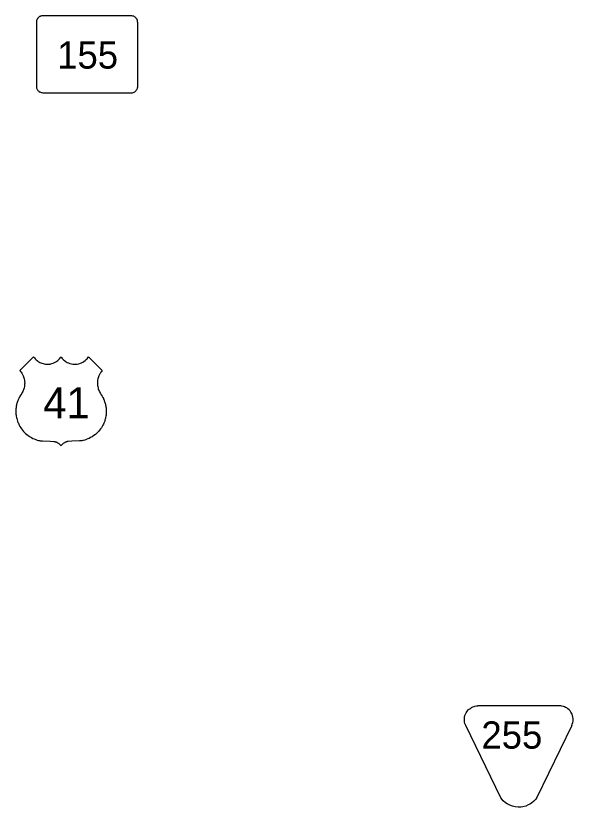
# Model space of a CAD drawing. Extents: x 1612280 to 1883141, y 560852 to 780851.
# Drawn here: x 1762915 to 1770463, y 642827 to 653552 of the extents above; entities that cross this region are included whole.
import ezdxf

# ---------------------------------------------------------------- set-up
doc = ezdxf.new("R2010")
doc.units = 0
for name, color, linetype in [('DESIGN - ROW - Easement Linework and Patterning', 7, 'Continuous'), ('DESIGN - ROW - Slope Lines', 7, 'Continuous'), ('SURVEY - DRAINAGE - Bridge Deck with Text', 7, 'Continuous')]:
    doc.layers.add(name, color=color, linetype=linetype)

msp = doc.modelspace()

# ---------------------------------------------------------------- linework, layer by layer
at = {"layer": 'DESIGN - ROW - Easement Linework and Patterning'}
for points in [[(1769482, 642953), (1769007, 643933), (1768997, 643960), (1768992, 643978), (1768989, 643996), (1768989, 644012), (1768989, 644030), (1768991, 644046), (1768997, 644069), (1769004, 644087), (1769012, 644103), (1769022, 644119), (1769032, 644133), (1769047, 644149), (1769062, 644161), (1769075, 644170), (1769088, 644178), (1769104, 644185), (1769120, 644191), (1769132, 644194), (1769154, 644198), (1769173, 644199)], [(1769482, 642953), (1769007, 643933), (1768997, 643960), (1768992, 643978), (1768989, 643996), (1768989, 644012), (1768989, 644030), (1768991, 644046), (1768997, 644069), (1769004, 644087), (1769012, 644103), (1769022, 644119), (1769032, 644133), (1769047, 644149), (1769062, 644161), (1769075, 644170), (1769088, 644178), (1769104, 644185), (1769120, 644191), (1769132, 644194), (1769154, 644198), (1769173, 644199)], [(1770444, 643933), (1770450, 643951), (1770458, 643974), (1770461, 643991), (1770463, 644011), (1770462, 644027), (1770460, 644045), (1770455, 644067), (1770448, 644085), (1770441, 644100), (1770433, 644115), (1770421, 644131), (1770409, 644144), (1770390, 644161), (1770375, 644171), (1770361, 644179), (1770347, 644185), (1770330, 644191), (1770311, 644196), (1770297, 644198), (1770278, 644199), (1769173, 644199)], [(1770444, 643933), (1770450, 643951), (1770458, 643974), (1770461, 643991), (1770463, 644011), (1770462, 644027), (1770460, 644045), (1770455, 644067), (1770448, 644085), (1770441, 644100), (1770433, 644115), (1770421, 644131), (1770409, 644144), (1770390, 644161), (1770375, 644171), (1770361, 644179), (1770347, 644185), (1770330, 644191), (1770311, 644196), (1770297, 644198), (1770278, 644199), (1769173, 644199)], [(1770444, 643933), (1769971, 642956), (1769956, 642936), (1769941, 642919), (1769928, 642906), (1769900, 642883), (1769878, 642868), (1769854, 642856), (1769821, 642842), (1769783, 642832), (1769752, 642828), (1769717, 642827), (1769679, 642830), (1769639, 642839), (1769603, 642853), (1769568, 642872), (1769546, 642887), (1769516, 642912), (1769482, 642953)], [(1770444, 643933), (1769971, 642956), (1769956, 642936), (1769941, 642919), (1769928, 642906), (1769900, 642883), (1769878, 642868), (1769854, 642856), (1769821, 642842), (1769783, 642832), (1769752, 642828), (1769717, 642827), (1769679, 642830), (1769639, 642839), (1769603, 642853), (1769568, 642872), (1769546, 642887), (1769516, 642912), (1769482, 642953)]]:
    msp.add_lwpolyline(points, dxfattribs=at)
at = {"layer": 'DESIGN - ROW - Slope Lines'}
msp.add_line((1763193, 653451), (1763193, 652619), dxfattribs=at)
msp.add_line((1763193, 653451), (1763193, 652619), dxfattribs=at)
for points in [[(1764566, 653440), (1764565, 653448), (1764565, 653456), (1764564, 653471), (1764563, 653481), (1764561, 653492), (1764559, 653498), (1764556, 653505), (1764551, 653512), (1764546, 653519), (1764541, 653525), (1764535, 653530), (1764531, 653534), (1764524, 653539), (1764519, 653542), (1764511, 653546), (1764505, 653548), (1764498, 653549), (1764488, 653551), (1764480, 653552), (1764472, 653552), (1764459, 653552), (1764450, 653552), (1763293, 653552), (1763283, 653552), (1763273, 653551), (1763264, 653550), (1763255, 653549), (1763250, 653547), (1763243, 653544), (1763237, 653541), (1763232, 653538), (1763223, 653531), (1763217, 653525), (1763211, 653519), (1763207, 653514), (1763202, 653504), (1763198, 653497), (1763196, 653492), (1763196, 653488), (1763195, 653485), (1763194, 653477), (1763193, 653468), (1763193, 653460), (1763193, 653453), (1763193, 653436)], [(1764566, 653440), (1764565, 653448), (1764565, 653456), (1764564, 653471), (1764563, 653481), (1764561, 653492), (1764559, 653498), (1764556, 653505), (1764551, 653512), (1764546, 653519), (1764541, 653525), (1764535, 653530), (1764531, 653534), (1764524, 653539), (1764519, 653542), (1764511, 653546), (1764505, 653548), (1764498, 653549), (1764488, 653551), (1764480, 653552), (1764472, 653552), (1764459, 653552), (1764450, 653552), (1763293, 653552), (1763283, 653552), (1763273, 653551), (1763264, 653550), (1763255, 653549), (1763250, 653547), (1763243, 653544), (1763237, 653541), (1763232, 653538), (1763223, 653531), (1763217, 653525), (1763211, 653519), (1763207, 653514), (1763202, 653504), (1763198, 653497), (1763196, 653492), (1763196, 653488), (1763195, 653485), (1763194, 653477), (1763193, 653468), (1763193, 653460), (1763193, 653453), (1763193, 653436)], [(1764456, 652510), (1764476, 652510), (1764493, 652510), (1764504, 652513), (1764516, 652517), (1764527, 652524), (1764536, 652531), (1764544, 652539), (1764550, 652547), (1764556, 652556), (1764560, 652564), (1764562, 652571), (1764564, 652579), (1764565, 652587), (1764565, 652597), (1764566, 652620), (1764566, 653440)], [(1764456, 652510), (1764476, 652510), (1764493, 652510), (1764504, 652513), (1764516, 652517), (1764527, 652524), (1764536, 652531), (1764544, 652539), (1764550, 652547), (1764556, 652556), (1764560, 652564), (1764562, 652571), (1764564, 652579), (1764565, 652587), (1764565, 652597), (1764566, 652620), (1764566, 653440)], [(1763193, 652619), (1763193, 652610), (1763193, 652600), (1763194, 652590), (1763195, 652581), (1763197, 652572), (1763199, 652564), (1763203, 652557), (1763207, 652550), (1763213, 652542), (1763218, 652536), (1763226, 652530), (1763233, 652524), (1763241, 652520), (1763249, 652516), (1763258, 652512), (1763265, 652512), (1763280, 652510), (1763299, 652510), (1764456, 652510)], [(1763193, 652619), (1763193, 652610), (1763193, 652600), (1763194, 652590), (1763195, 652581), (1763197, 652572), (1763199, 652564), (1763203, 652557), (1763207, 652550), (1763213, 652542), (1763218, 652536), (1763226, 652530), (1763233, 652524), (1763241, 652520), (1763249, 652516), (1763258, 652512), (1763265, 652512), (1763280, 652510), (1763299, 652510), (1764456, 652510)]]:
    msp.add_lwpolyline(points, dxfattribs=at)
at = {"layer": 'SURVEY - DRAINAGE - Bridge Deck with Text'}
for points in [[(1762969, 648744), (1763156, 648930), (1763166, 648916), (1763178, 648902), (1763191, 648890), (1763202, 648880), (1763214, 648870), (1763227, 648862), (1763239, 648855), (1763254, 648848), (1763267, 648843), (1763283, 648838), (1763299, 648834), (1763315, 648831), (1763333, 648830), (1763341, 648830), (1763349, 648830), (1763357, 648830), (1763367, 648831), (1763378, 648833), (1763391, 648835), (1763404, 648838), (1763422, 648845), (1763439, 648852), (1763456, 648861), (1763469, 648870), (1763483, 648881), (1763496, 648892), (1763508, 648905), (1763520, 648919), (1763528, 648930), (1763534, 648920), (1763543, 648909), (1763551, 648900), (1763560, 648891), (1763572, 648880), (1763585, 648871), (1763598, 648862), (1763611, 648854), (1763627, 648847), (1763646, 648840), (1763667, 648835), (1763688, 648831), (1763706, 648830), (1763726, 648830), (1763746, 648832), (1763766, 648836), (1763789, 648843), (1763806, 648850), (1763821, 648858), (1763838, 648868), (1763852, 648879), (1763868, 648893), (1763879, 648904), (1763889, 648916), (1763899, 648930), (1764085, 648744)], [(1762969, 648744), (1763156, 648930), (1763166, 648916), (1763178, 648902), (1763191, 648890), (1763202, 648880), (1763214, 648870), (1763227, 648862), (1763239, 648855), (1763254, 648848), (1763267, 648843), (1763283, 648838), (1763299, 648834), (1763315, 648831), (1763333, 648830), (1763341, 648830), (1763349, 648830), (1763357, 648830), (1763367, 648831), (1763378, 648833), (1763391, 648835), (1763404, 648838), (1763422, 648845), (1763439, 648852), (1763456, 648861), (1763469, 648870), (1763483, 648881), (1763496, 648892), (1763508, 648905), (1763520, 648919), (1763528, 648930), (1763534, 648920), (1763543, 648909), (1763551, 648900), (1763560, 648891), (1763572, 648880), (1763585, 648871), (1763598, 648862), (1763611, 648854), (1763627, 648847), (1763646, 648840), (1763667, 648835), (1763688, 648831), (1763706, 648830), (1763726, 648830), (1763746, 648832), (1763766, 648836), (1763789, 648843), (1763806, 648850), (1763821, 648858), (1763838, 648868), (1763852, 648879), (1763868, 648893), (1763879, 648904), (1763889, 648916), (1763899, 648930), (1764085, 648744)], [(1762969, 648744), (1762978, 648733), (1762986, 648722), (1762994, 648711), (1763000, 648701), (1763007, 648689), (1763013, 648675), (1763019, 648661), (1763024, 648645), (1763028, 648631), (1763031, 648615), (1763034, 648597), (1763035, 648575), (1763034, 648559), (1763033, 648543), (1763031, 648529), (1763027, 648511), (1763023, 648497), (1763018, 648484), (1763013, 648472), (1763009, 648461), (1763001, 648448), (1762994, 648435), (1762983, 648417), (1762970, 648396), (1762967, 648390), (1762961, 648379), (1762954, 648366), (1762950, 648357), (1762945, 648346), (1762941, 648335), (1762937, 648324), (1762933, 648313), (1762930, 648300), (1762926, 648287), (1762924, 648275), (1762921, 648263), (1762919, 648252), (1762918, 648239), (1762916, 648227), (1762916, 648216), (1762915, 648205), (1762915, 648194), (1762915, 648181), (1762916, 648170), (1762917, 648155), (1762918, 648140), (1762921, 648125), (1762923, 648110), (1762927, 648094), (1762932, 648075), (1762937, 648060), (1762943, 648042), (1762949, 648029), (1762954, 648017), (1762962, 648003), (1762971, 647985), (1762981, 647970), (1762993, 647953), (1763005, 647936), (1763019, 647920), (1763033, 647905), (1763046, 647893), (1763063, 647878), (1763082, 647863), (1763107, 647847), (1763127, 647835), (1763146, 647825), (1763164, 647817), (1763185, 647809), (1763205, 647802), (1763224, 647797), (1763234, 647795), (1763246, 647793), (1763277, 647790), (1763382, 647787), (1763430, 647785), (1763434, 647784), (1763439, 647783), (1763444, 647782), (1763449, 647780), (1763454, 647779), (1763459, 647777), (1763464, 647775), (1763468, 647773), (1763473, 647770), (1763477, 647768), (1763481, 647766), (1763490, 647761), (1763499, 647754), (1763508, 647746), (1763515, 647739), (1763522, 647732), (1763527, 647723)], [(1762969, 648744), (1762978, 648733), (1762986, 648722), (1762994, 648711), (1763000, 648701), (1763007, 648689), (1763013, 648675), (1763019, 648661), (1763024, 648645), (1763028, 648631), (1763031, 648615), (1763034, 648597), (1763035, 648575), (1763034, 648559), (1763033, 648543), (1763031, 648529), (1763027, 648511), (1763023, 648497), (1763018, 648484), (1763013, 648472), (1763009, 648461), (1763001, 648448), (1762994, 648435), (1762983, 648417), (1762970, 648396), (1762967, 648390), (1762961, 648379), (1762954, 648366), (1762950, 648357), (1762945, 648346), (1762941, 648335), (1762937, 648324), (1762933, 648313), (1762930, 648300), (1762926, 648287), (1762924, 648275), (1762921, 648263), (1762919, 648252), (1762918, 648239), (1762916, 648227), (1762916, 648216), (1762915, 648205), (1762915, 648194), (1762915, 648181), (1762916, 648170), (1762917, 648155), (1762918, 648140), (1762921, 648125), (1762923, 648110), (1762927, 648094), (1762932, 648075), (1762937, 648060), (1762943, 648042), (1762949, 648029), (1762954, 648017), (1762962, 648003), (1762971, 647985), (1762981, 647970), (1762993, 647953), (1763005, 647936), (1763019, 647920), (1763033, 647905), (1763046, 647893), (1763063, 647878), (1763082, 647863), (1763107, 647847), (1763127, 647835), (1763146, 647825), (1763164, 647817), (1763185, 647809), (1763205, 647802), (1763224, 647797), (1763234, 647795), (1763246, 647793), (1763277, 647790), (1763382, 647787), (1763430, 647785), (1763434, 647784), (1763439, 647783), (1763444, 647782), (1763449, 647780), (1763454, 647779), (1763459, 647777), (1763464, 647775), (1763468, 647773), (1763473, 647770), (1763477, 647768), (1763481, 647766), (1763490, 647761), (1763499, 647754), (1763508, 647746), (1763515, 647739), (1763522, 647732), (1763527, 647723)], [(1764085, 648744), (1764076, 648733), (1764068, 648722), (1764061, 648711), (1764054, 648701), (1764047, 648689), (1764041, 648675), (1764035, 648661), (1764030, 648645), (1764026, 648631), (1764023, 648615), (1764021, 648597), (1764020, 648575), (1764020, 648559), (1764022, 648543), (1764024, 648529), (1764028, 648511), (1764031, 648497), (1764036, 648484), (1764041, 648472), (1764046, 648461), (1764053, 648448), (1764061, 648435), (1764071, 648417), (1764084, 648396), (1764088, 648390), (1764094, 648379), (1764100, 648366), (1764104, 648357), (1764109, 648346), (1764113, 648335), (1764117, 648324), (1764121, 648313), (1764125, 648300), (1764128, 648287), (1764131, 648276), (1764133, 648263), (1764135, 648252), (1764137, 648239), (1764138, 648227), (1764139, 648216), (1764139, 648205), (1764139, 648194), (1764139, 648181), (1764139, 648170), (1764138, 648155), (1764136, 648140), (1764134, 648125), (1764131, 648110), (1764127, 648094), (1764122, 648075), (1764118, 648060), (1764111, 648042), (1764105, 648029), (1764100, 648017), (1764093, 648003), (1764083, 647985), (1764074, 647970), (1764062, 647953), (1764049, 647936), (1764036, 647920), (1764021, 647905), (1764009, 647893), (1763992, 647878), (1763972, 647863), (1763948, 647847), (1763927, 647835), (1763908, 647825), (1763890, 647817), (1763869, 647809), (1763850, 647802), (1763831, 647797), (1763821, 647795), (1763808, 647793), (1763778, 647790), (1763672, 647787), (1763625, 647785), (1763620, 647784), (1763615, 647783), (1763610, 647782), (1763605, 647780), (1763600, 647779), (1763596, 647777), (1763590, 647775), (1763586, 647773), (1763581, 647770), (1763577, 647768), (1763573, 647766), (1763564, 647761), (1763555, 647754), (1763547, 647746), (1763539, 647739), (1763533, 647732), (1763527, 647723)], [(1764085, 648744), (1764076, 648733), (1764068, 648722), (1764061, 648711), (1764054, 648701), (1764047, 648689), (1764041, 648675), (1764035, 648661), (1764030, 648645), (1764026, 648631), (1764023, 648615), (1764021, 648597), (1764020, 648575), (1764020, 648559), (1764022, 648543), (1764024, 648529), (1764028, 648511), (1764031, 648497), (1764036, 648484), (1764041, 648472), (1764046, 648461), (1764053, 648448), (1764061, 648435), (1764071, 648417), (1764084, 648396), (1764088, 648390), (1764094, 648379), (1764100, 648366), (1764104, 648357), (1764109, 648346), (1764113, 648335), (1764117, 648324), (1764121, 648313), (1764125, 648300), (1764128, 648287), (1764131, 648276), (1764133, 648263), (1764135, 648252), (1764137, 648239), (1764138, 648227), (1764139, 648216), (1764139, 648205), (1764139, 648194), (1764139, 648181), (1764139, 648170), (1764138, 648155), (1764136, 648140), (1764134, 648125), (1764131, 648110), (1764127, 648094), (1764122, 648075), (1764118, 648060), (1764111, 648042), (1764105, 648029), (1764100, 648017), (1764093, 648003), (1764083, 647985), (1764074, 647970), (1764062, 647953), (1764049, 647936), (1764036, 647920), (1764021, 647905), (1764009, 647893), (1763992, 647878), (1763972, 647863), (1763948, 647847), (1763927, 647835), (1763908, 647825), (1763890, 647817), (1763869, 647809), (1763850, 647802), (1763831, 647797), (1763821, 647795), (1763808, 647793), (1763778, 647790), (1763672, 647787), (1763625, 647785), (1763620, 647784), (1763615, 647783), (1763610, 647782), (1763605, 647780), (1763600, 647779), (1763596, 647777), (1763590, 647775), (1763586, 647773), (1763581, 647770), (1763577, 647768), (1763573, 647766), (1763564, 647761), (1763555, 647754), (1763547, 647746), (1763539, 647739), (1763533, 647732), (1763527, 647723)]]:
    msp.add_lwpolyline(points, dxfattribs=at)

# ---------------------------------------------------------------- texts
at = {"layer": 'DESIGN - ROW - Easement Linework and Patterning'}
msp.add_text('255', height=369.6, rotation=0.0012, dxfattribs=at).set_placement((1769220, 643620))
msp.add_text('255', height=369.6, rotation=0.0012, dxfattribs=at).set_placement((1769220, 643620))
at = {"layer": 'DESIGN - ROW - Slope Lines'}
msp.add_text('155', height=369.6, rotation=0.0011, dxfattribs=at).set_placement((1763475, 652837))
msp.add_text('155', height=369.6, rotation=0.0011, dxfattribs=at).set_placement((1763475, 652837))
at = {"layer": 'SURVEY - DRAINAGE - Bridge Deck with Text'}
msp.add_text('41', height=422.4, rotation=0.0013, dxfattribs=at).set_placement((1763286, 648096))
msp.add_text('41', height=422.4, rotation=0.0013, dxfattribs=at).set_placement((1763286, 648096))

doc.saveas('drawing.dxf')
